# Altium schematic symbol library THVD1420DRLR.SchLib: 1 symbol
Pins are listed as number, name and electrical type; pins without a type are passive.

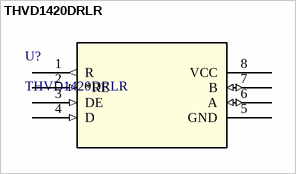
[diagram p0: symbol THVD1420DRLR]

## THVD1420DRLR
designator U?
3.3-V to 5-V, 12-Mbps, RS-485 transceiver in small package option with &plusmn;12-kV IEC ESD prot 8-SOT-5X3 -40 to 125; Manufacturer_Name: Texas Instruments
footprint SOT5X3-8_DRL_TEX
pins: 1 R (out), 2 *RE (in), 3 DE (in), 4 D (in), 5 GND (power), 6 A (io), 7 B (io), 8 VCC (power)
